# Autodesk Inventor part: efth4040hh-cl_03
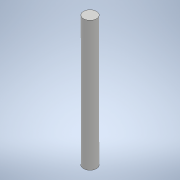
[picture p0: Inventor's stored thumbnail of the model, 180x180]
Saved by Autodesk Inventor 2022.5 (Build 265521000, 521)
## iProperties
Part Number: efth4040hh-cl_03
Material: 一般
Document SubType Name: Modeling
Designer: ImaoCorp
Density: 1 g/cm^3
Appearance: 既定
Author: ImaoCorp
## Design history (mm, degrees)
feature "efth4040hh-cl_03"
node "ソリッド1"
